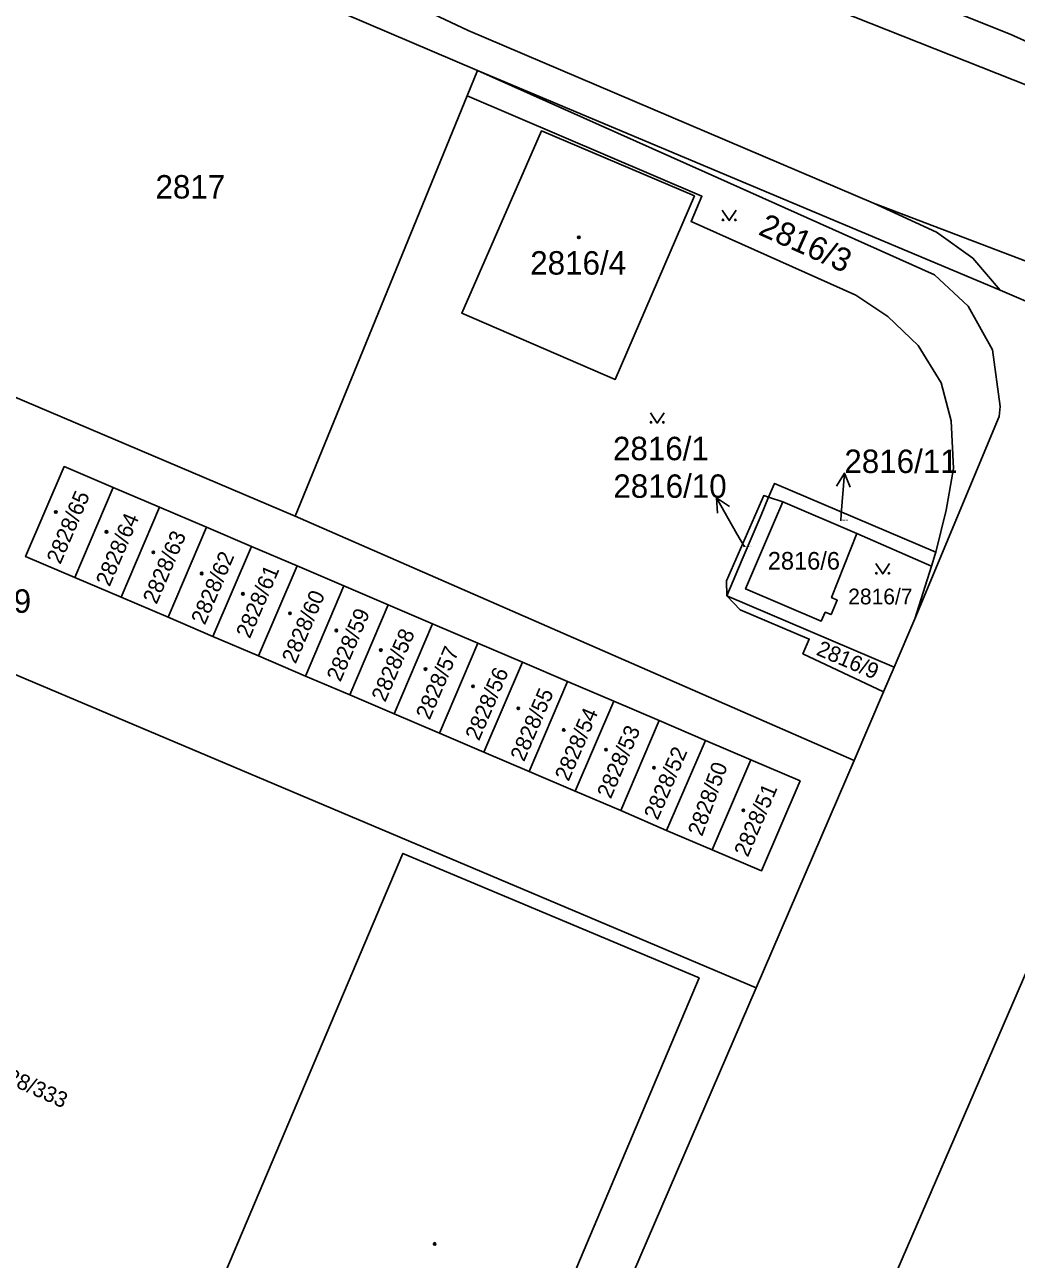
# Model space of a CAD drawing. Extents: x -596024 to -594475, y -1163820 to -1161957.
# Drawn here: x -594768.7 to -594696.7, y -1162300.1 to -1162210.5 of the extents above; entities that cross this region are included whole.
import ezdxf

# ---------------------------------------------------------------- set-up
doc = ezdxf.new("R2010")
doc.units = 0
for name, color, linetype in [('Level 1', 7, 'Continuous'), ('Level 4', 7, 'Continuous'), ('Level 5', 7, 'Continuous'), ('Level 57', 7, 'Continuous'), ('Level 60', 7, 'Continuous'), ('Vrstva 60', 7, 'Continuous')]:
    doc.layers.add(name, color=color, linetype=linetype)

msp = doc.modelspace()

# ---------------------------------------------------------------- linework, layer by layer
at = {"layer": 'Level 1'}
for points in [[(-594707.09, -1162223.48), (-594736.5, -1162210.95), (-594743.11, -1162207.81), (-594746.4, -1162206.15), (-594756.91, -1162200.41), (-594760.53, -1162198.75), (-594767.3, -1162195.88), (-594768.99, -1162199.68)], [(-594766.55, -1162200.72), (-594735.81, -1162213.85)], [(-594727.84, -1162201.98), (-594709.6, -1162209.52), (-594675.03, -1162223.23)], [(-594682.35, -1162217.53), (-594689.64, -1162214.64), (-594697.18, -1162211.23), (-594701.73, -1162209.41)], [(-594736.56, -1162215.7), (-594735.81, -1162213.85)], [(-594735.81, -1162213.85), (-594697.92, -1162229.81)], [(-594704.11, -1162253.66), (-594697.99, -1162238.96), (-594697.9, -1162238.25), (-594698.47, -1162234.14), (-594700.22, -1162230.95), (-594702.66, -1162228.69), (-594719.3, -1162221.23), (-594735.81, -1162213.85)], [(-594749.03, -1162246.2), (-594736.56, -1162215.7)], [(-594736.56, -1162215.7), (-594719.54, -1162222.99), (-594720.33, -1162224.82), (-594708.38, -1162230.17), (-594706.06, -1162231.71), (-594703.86, -1162233.81), (-594702.18, -1162236.53), (-594701.46, -1162239.29), (-594701.29, -1162242.73), (-594701.83, -1162245.76), (-594702.58, -1162248.81)], [(-594725.83, -1162236.28), (-594736.96, -1162231.48), (-594731.18, -1162218.24), (-594720.08, -1162222.96), (-594725.83, -1162236.28)], [(-594665.22, -1162239.43), (-594707.09, -1162223.48)], [(-594697.92, -1162229.81), (-594699.9, -1162227.48), (-594702.53, -1162225.59), (-594707.09, -1162223.48)], [(-594697.92, -1162229.81), (-594677.27, -1162238.66)], [(-594779.95, -1162233.06), (-594749.03, -1162246.2)], [(-594762.23, -1162244.12), (-594765.8, -1162242.6), (-594768.59, -1162249.13), (-594765.02, -1162250.66)], [(-594762.23, -1162244.12), (-594765.02, -1162250.66)], [(-594758.87, -1162245.55), (-594762.23, -1162244.12)], [(-594714.7, -1162244.83), (-594714.27, -1162243.83), (-594702.58, -1162248.81)], [(-594761.66, -1162252.08), (-594758.87, -1162245.55)], [(-594755.47, -1162247.01), (-594758.87, -1162245.55)], [(-594717.74, -1162251.98), (-594717.76, -1162250.89), (-594715.06, -1162244.71), (-594714.7, -1162244.83)], [(-594714.7, -1162244.83), (-594715.25, -1162246.14), (-594716.62, -1162249.35), (-594717.74, -1162251.98)], [(-594713.68, -1162245.17), (-594714.28, -1162246.56), (-594715.65, -1162249.78), (-594716.37, -1162251.48), (-594710.88, -1162253.82), (-594710.59, -1162253.17), (-594710.17, -1162253.34), (-594709.72, -1162252.3), (-594710.14, -1162252.11), (-594708.3, -1162247.46)], [(-594714.7, -1162244.83), (-594713.68, -1162245.17)], [(-594708.3, -1162247.46), (-594713.68, -1162245.17)], [(-594749.03, -1162246.2), (-594708.5, -1162263.93)], [(-594758.26, -1162253.54), (-594755.47, -1162247.01)], [(-594752.21, -1162248.4), (-594755.47, -1162247.01)], [(-594708.3, -1162247.46), (-594702.89, -1162249.82)], [(-594755, -1162254.93), (-594752.21, -1162248.4)], [(-594748.9, -1162249.81), (-594752.21, -1162248.4)], [(-594702.89, -1162249.82), (-594702.62, -1162248.97), (-594702.58, -1162248.81)], [(-594715.61, -1162280.43), (-594788.46, -1162249.61), (-594788.63, -1162249.99)], [(-594751.69, -1162256.34), (-594748.9, -1162249.81)], [(-594745.5, -1162251.26), (-594748.9, -1162249.81)], [(-594702.89, -1162249.82), (-594704.11, -1162253.66)], [(-594765.02, -1162250.66), (-594761.66, -1162252.08)], [(-594748.29, -1162257.8), (-594745.5, -1162251.26)], [(-594742.29, -1162252.64), (-594745.5, -1162251.26)], [(-594761.66, -1162252.08), (-594758.26, -1162253.54)], [(-594745.08, -1162259.17), (-594742.29, -1162252.64)], [(-594739.07, -1162254.01), (-594742.29, -1162252.64)], [(-594706.36, -1162258.94), (-594712.21, -1162256.18), (-594711.75, -1162255.12), (-594716.76, -1162253.01), (-594717.74, -1162251.98)], [(-594705.6, -1162257.16), (-594717.74, -1162251.98)], [(-594758.26, -1162253.54), (-594755, -1162254.93)], [(-594741.87, -1162260.54), (-594739.07, -1162254.01)], [(-594735.79, -1162255.41), (-594739.07, -1162254.01)], [(-594705.6, -1162257.16), (-594704.11, -1162253.66)], [(-594755, -1162254.93), (-594751.69, -1162256.34)], [(-594735.79, -1162255.41), (-594738.58, -1162261.94)], [(-594732.55, -1162256.8), (-594735.79, -1162255.41)], [(-594751.69, -1162256.34), (-594748.29, -1162257.8)], [(-594735.35, -1162263.33), (-594732.55, -1162256.8)], [(-594729.28, -1162258.19), (-594732.55, -1162256.8)], [(-594706.36, -1162258.94), (-594705.6, -1162257.16)], [(-594748.29, -1162257.8), (-594745.08, -1162259.17)], [(-594729.28, -1162258.19), (-594732.08, -1162264.72)], [(-594725.93, -1162259.63), (-594729.28, -1162258.19)], [(-594708.5, -1162263.93), (-594706.36, -1162258.94)], [(-594745.08, -1162259.17), (-594741.87, -1162260.54)], [(-594728.73, -1162266.16), (-594725.93, -1162259.63)], [(-594722.63, -1162261.04), (-594725.93, -1162259.63)], [(-594741.87, -1162260.54), (-594738.58, -1162261.94)], [(-594725.42, -1162267.57), (-594722.63, -1162261.04)], [(-594722.63, -1162261.04), (-594719.28, -1162262.47)], [(-594738.58, -1162261.94), (-594735.35, -1162263.33)], [(-594722.1, -1162269), (-594719.28, -1162262.47)], [(-594719.28, -1162262.47), (-594716, -1162263.88)], [(-594735.35, -1162263.33), (-594732.08, -1162264.72)], [(-594716, -1162263.88), (-594712.42, -1162265.41), (-594715.22, -1162271.94), (-594718.79, -1162270.41)], [(-594716, -1162263.88), (-594718.79, -1162270.41)], [(-594715.61, -1162280.43), (-594708.5, -1162263.93)], [(-594732.08, -1162264.72), (-594728.73, -1162266.16)], [(-594728.73, -1162266.16), (-594725.42, -1162267.57)], [(-594722.1, -1162269), (-594725.42, -1162267.57)], [(-594718.79, -1162270.41), (-594722.1, -1162269)], [(-594765.42, -1162327.81), (-594741.23, -1162270.67), (-594719.75, -1162279.71), (-594743.92, -1162336.9)], [(-594734.83, -1162369.04), (-594734.38, -1162367.99), (-594695.58, -1162278.29)], [(-594715.61, -1162280.43), (-594744.57, -1162347.6), (-594746.96, -1162353.57)]]:
    msp.add_lwpolyline(points, dxfattribs=at)
at = {"layer": 'Level 5'}
for points in [[(-594718.061, -1162224), (-594717.56, -1162224.75), (-594717.06, -1162224)], [(-594723.281, -1162238.69), (-594722.78, -1162239.44), (-594722.28, -1162238.69)], [(-594706.931, -1162249.64), (-594706.43, -1162250.39), (-594705.93, -1162249.64)]]:
    msp.add_lwpolyline(points, dxfattribs=at)
for centre, radius in [((-594718.01, -1162224.7), 0.05), ((-594717.111, -1162224.7), 0.05), ((-594728.47, -1162225.97), 0.09), ((-594728.47, -1162225.97), 0.0521), ((-594723.23, -1162239.39), 0.05), ((-594722.331, -1162239.39), 0.05), ((-594766.4, -1162245.9), 0.09), ((-594766.4, -1162245.9), 0.0521), ((-594762.72, -1162247.34), 0.09), ((-594762.72, -1162247.34), 0.0521), ((-594759.32, -1162248.83), 0.09), ((-594759.32, -1162248.83), 0.0521), ((-594755.82, -1162250.36), 0.09), ((-594755.82, -1162250.36), 0.0521), ((-594706.88, -1162250.34), 0.05), ((-594705.981, -1162250.34), 0.05), ((-594752.83, -1162251.84), 0.09), ((-594752.83, -1162251.84), 0.0521), ((-594749.42, -1162253.25), 0.09), ((-594749.42, -1162253.25), 0.0521), ((-594746.05, -1162254.5), 0.09), ((-594746.05, -1162254.5), 0.0521), ((-594742.83, -1162255.92), 0.09), ((-594742.83, -1162255.92), 0.0521), ((-594739.59, -1162257.3), 0.09), ((-594739.59, -1162257.3), 0.0521), ((-594736.14, -1162258.55), 0.09), ((-594736.14, -1162258.55), 0.0521), ((-594732.86, -1162260.15), 0.09), ((-594732.86, -1162260.15), 0.0521), ((-594729.56, -1162261.71), 0.09), ((-594729.56, -1162261.71), 0.0521), ((-594726.49, -1162263.14), 0.09), ((-594726.49, -1162263.14), 0.0521), ((-594723.02, -1162264.46), 0.09), ((-594723.02, -1162264.46), 0.0521), ((-594716.53, -1162267.55), 0.09), ((-594716.53, -1162267.55), 0.0521), ((-594738.92, -1162299.01), 0.09), ((-594738.92, -1162299.01), 0.0521)]:
    msp.add_circle(centre, radius, dxfattribs=at)
at = {"layer": 'Level 57'}
for p, q in [((-594709.434, -1162246.062), (-594709.21, -1162243.07)), ((-594716.998, -1162247.48), (-594718.476, -1162244.87)), ((-594709.47, -1162246.54), (-594709.434, -1162246.062)), ((-594716.46, -1162248.43), (-594716.998, -1162247.48))]:
    msp.add_line(p, q, dxfattribs=at)
for points in [[(-594709.783, -1162244.03), (-594709.21, -1162243.07), (-594708.786, -1162244.105)], [(-594718.419, -1162245.986), (-594718.476, -1162244.87), (-594717.549, -1162245.493)]]:
    msp.add_lwpolyline(points, dxfattribs=at)
at = {"layer": 'Level 60'}
for points in [[(-594689.64, -1162214.64), (-594697.18, -1162211.23), (-594701.73, -1162209.41), (-594652.12, -1162083.97), (-594635.64, -1162042.29), (-594631.38, -1162044.42), (-594625.07, -1162047.82), (-594653.97, -1162133.18), (-594655.49, -1162137.69), (-594667.25, -1162133.63), (-594675.19, -1162156.64), (-594678.9, -1162155.36), (-594685.92, -1162175.69), (-594674.83, -1162179.48), (-594670.08, -1162165.57), (-594665.39, -1162167.12), (-594682.35, -1162217.53)], [(-594702.53, -1162225.59), (-594699.9, -1162227.48), (-594697.92, -1162229.81), (-594735.81, -1162213.85), (-594766.55, -1162200.72), (-594768.99, -1162199.68), (-594767.3, -1162195.88), (-594760.53, -1162198.75), (-594756.91, -1162200.41), (-594746.4, -1162206.15), (-594743.11, -1162207.81), (-594736.5, -1162210.95), (-594707.09, -1162223.48)], [(-594697.18, -1162211.23), (-594689.64, -1162214.64), (-594682.35, -1162217.53), (-594681.39, -1162217.94), (-594669.86, -1162222.85), (-594671.99, -1162223.53), (-594675.03, -1162223.23), (-594709.6, -1162209.52), (-594727.84, -1162201.98), (-594728.96, -1162200.3), (-594730.51, -1162196.79), (-594727.89, -1162197.94), (-594720, -1162201.49), (-594718.63, -1162202.1), (-594713.96, -1162204.17), (-594705.43, -1162207.92), (-594701.73, -1162209.41)], [(-594735.81, -1162213.85), (-594736.56, -1162215.7), (-594749.03, -1162246.2), (-594779.95, -1162233.06), (-594766.55, -1162200.72)], [(-594816.82, -1162217.1), (-594798.1, -1162225.02), (-594779.95, -1162233.06), (-594749.03, -1162246.2), (-594708.5, -1162263.93), (-594715.61, -1162280.43), (-594788.46, -1162249.61), (-594788.63, -1162249.99), (-594837.24, -1162227.82), (-594832.36, -1162216.61), (-594829.67, -1162211.66)], [(-594697.99, -1162238.96), (-594704.11, -1162253.66), (-594702.89, -1162249.82), (-594702.62, -1162248.97), (-594702.58, -1162248.81), (-594701.83, -1162245.76), (-594701.29, -1162242.73), (-594701.46, -1162239.29), (-594702.18, -1162236.53), (-594703.86, -1162233.81), (-594706.06, -1162231.71), (-594708.38, -1162230.17), (-594720.33, -1162224.82), (-594719.54, -1162222.99), (-594736.56, -1162215.7), (-594735.81, -1162213.85), (-594719.3, -1162221.23), (-594702.66, -1162228.69), (-594700.22, -1162230.95), (-594698.47, -1162234.14), (-594697.9, -1162238.25)], [(-594708.38, -1162230.17), (-594706.06, -1162231.71), (-594703.86, -1162233.81), (-594702.18, -1162236.53), (-594701.46, -1162239.29), (-594701.29, -1162242.73), (-594701.83, -1162245.76), (-594702.58, -1162248.81), (-594714.27, -1162243.83), (-594714.7, -1162244.83), (-594715.06, -1162244.71), (-594717.76, -1162250.89), (-594717.74, -1162251.98), (-594716.76, -1162253.01), (-594711.75, -1162255.12), (-594712.21, -1162256.18), (-594706.36, -1162258.94), (-594708.5, -1162263.93), (-594749.03, -1162246.2), (-594736.56, -1162215.7), (-594719.54, -1162222.99), (-594720.33, -1162224.82)], [(-594736.96, -1162231.48), (-594725.83, -1162236.28), (-594720.08, -1162222.96), (-594731.18, -1162218.24)], [(-594725.83, -1162236.28), (-594736.96, -1162231.48), (-594731.18, -1162218.24), (-594720.08, -1162222.96)], [(-594676.95, -1162238.57), (-594677.27, -1162238.66), (-594697.92, -1162229.81), (-594699.9, -1162227.48), (-594702.53, -1162225.59), (-594707.09, -1162223.48), (-594665.22, -1162239.43), (-594668.99, -1162238.31), (-594673, -1162237.9)], [(-594765.02, -1162250.66), (-594761.66, -1162252.08), (-594758.26, -1162253.54), (-594755, -1162254.93), (-594751.69, -1162256.34), (-594748.29, -1162257.8), (-594745.08, -1162259.17), (-594741.87, -1162260.54), (-594738.58, -1162261.94), (-594735.35, -1162263.33), (-594732.08, -1162264.72), (-594728.73, -1162266.16), (-594725.42, -1162267.57), (-594722.1, -1162269), (-594718.79, -1162270.41), (-594715.22, -1162271.94), (-594712.42, -1162265.41), (-594716, -1162263.88), (-594719.28, -1162262.47), (-594722.63, -1162261.04), (-594725.93, -1162259.63), (-594729.28, -1162258.19), (-594732.55, -1162256.8), (-594735.79, -1162255.41), (-594739.07, -1162254.01), (-594742.29, -1162252.64), (-594745.5, -1162251.26), (-594748.9, -1162249.81), (-594752.21, -1162248.4), (-594755.47, -1162247.01), (-594758.87, -1162245.55), (-594762.23, -1162244.12), (-594765.8, -1162242.6), (-594768.59, -1162249.13)], [(-594762.23, -1162244.12), (-594765.02, -1162250.66), (-594768.59, -1162249.13), (-594765.8, -1162242.6)], [(-594765.02, -1162250.66), (-594762.23, -1162244.12), (-594758.87, -1162245.55), (-594761.66, -1162252.08)], [(-594713.68, -1162245.17), (-594714.7, -1162244.83), (-594714.27, -1162243.83), (-594702.58, -1162248.81), (-594702.62, -1162248.97), (-594702.89, -1162249.82), (-594708.3, -1162247.46)], [(-594761.66, -1162252.08), (-594758.87, -1162245.55), (-594755.47, -1162247.01), (-594758.26, -1162253.54)], [(-594717.74, -1162251.98), (-594717.76, -1162250.89), (-594715.06, -1162244.71), (-594714.7, -1162244.83), (-594715.25, -1162246.14), (-594716.62, -1162249.35)], [(-594704.11, -1162253.66), (-594705.6, -1162257.16), (-594717.74, -1162251.98), (-594716.62, -1162249.35), (-594715.25, -1162246.14), (-594714.7, -1162244.83), (-594713.68, -1162245.17), (-594714.28, -1162246.56), (-594715.65, -1162249.78), (-594716.37, -1162251.48), (-594710.88, -1162253.82), (-594710.59, -1162253.17), (-594710.17, -1162253.34), (-594709.72, -1162252.3), (-594710.14, -1162252.11), (-594708.3, -1162247.46), (-594702.89, -1162249.82)], [(-594716.37, -1162251.48), (-594715.65, -1162249.78), (-594714.28, -1162246.56), (-594713.68, -1162245.17), (-594708.3, -1162247.46), (-594710.14, -1162252.11), (-594709.72, -1162252.3), (-594710.17, -1162253.34), (-594710.59, -1162253.17), (-594710.88, -1162253.82)], [(-594758.26, -1162253.54), (-594755.47, -1162247.01), (-594752.21, -1162248.4), (-594755, -1162254.93)], [(-594755, -1162254.93), (-594752.21, -1162248.4), (-594748.9, -1162249.81), (-594751.69, -1162256.34)], [(-594788.46, -1162249.61), (-594715.61, -1162280.43), (-594744.57, -1162347.6), (-594746.96, -1162353.57), (-594748.04, -1162354.24), (-594750.51, -1162354.75), (-594752.49, -1162354.29), (-594804.19, -1162332.35), (-594810.1, -1162329.79), (-594821.58, -1162324.95), (-594788.63, -1162249.99)], [(-594751.69, -1162256.34), (-594748.9, -1162249.81), (-594745.5, -1162251.26), (-594748.29, -1162257.8)], [(-594748.29, -1162257.8), (-594745.5, -1162251.26), (-594742.29, -1162252.64), (-594745.08, -1162259.17)], [(-594745.08, -1162259.17), (-594742.29, -1162252.64), (-594739.07, -1162254.01), (-594741.87, -1162260.54)], [(-594706.36, -1162258.94), (-594712.21, -1162256.18), (-594711.75, -1162255.12), (-594716.76, -1162253.01), (-594717.74, -1162251.98), (-594705.6, -1162257.16)], [(-594741.87, -1162260.54), (-594739.07, -1162254.01), (-594735.79, -1162255.41), (-594738.58, -1162261.94)], [(-594738.58, -1162261.94), (-594735.79, -1162255.41), (-594732.55, -1162256.8), (-594735.35, -1162263.33)], [(-594735.35, -1162263.33), (-594732.55, -1162256.8), (-594729.28, -1162258.19), (-594732.08, -1162264.72)], [(-594732.08, -1162264.72), (-594729.28, -1162258.19), (-594725.93, -1162259.63), (-594728.73, -1162266.16)], [(-594722.63, -1162261.04), (-594725.42, -1162267.57), (-594728.73, -1162266.16), (-594725.93, -1162259.63)], [(-594725.42, -1162267.57), (-594722.63, -1162261.04), (-594719.28, -1162262.47), (-594722.1, -1162269)], [(-594722.1, -1162269), (-594719.28, -1162262.47), (-594716, -1162263.88), (-594718.79, -1162270.41)], [(-594718.79, -1162270.41), (-594716, -1162263.88), (-594712.42, -1162265.41), (-594715.22, -1162271.94)], [(-594719.75, -1162279.71), (-594741.23, -1162270.67), (-594765.42, -1162327.81), (-594776.1, -1162323.11), (-594786.46, -1162332.09), (-594759.51, -1162343.51), (-594760.04, -1162344.72), (-594749.17, -1162349.3), (-594743.92, -1162336.9)], [(-594741.23, -1162270.67), (-594719.75, -1162279.71), (-594743.92, -1162336.9), (-594765.42, -1162327.81)], [(-594695.58, -1162278.29), (-594648.27, -1162298.38), (-594683.2, -1162380.56), (-594691.28, -1162377.35), (-594692.6, -1162380.36), (-594694.11, -1162382.09), (-594696.5, -1162383.23), (-594699.4, -1162383.25), (-594734.83, -1162369.04), (-594734.38, -1162367.99)]]:
    msp.add_lwpolyline(points, close=True, dxfattribs=at)
msp.add_lwpolyline([(-594744.57, -1162347.6), (-594715.61, -1162280.43), (-594708.5, -1162263.93), (-594706.36, -1162258.94), (-594705.6, -1162257.16), (-594704.11, -1162253.66), (-594697.99, -1162238.96), (-594697.9, -1162238.25), (-594698.47, -1162234.14), (-594700.22, -1162230.95), (-594702.66, -1162228.69), (-594719.3, -1162221.23), (-594735.81, -1162213.85), (-594697.92, -1162229.81), (-594677.27, -1162238.66), (-594672.61, -1162240.67), (-594676.36, -1162241.26), (-594678.88, -1162242.68), (-594680.93, -1162244.85), (-594683.14, -1162249.47), (-594689.11, -1162263.33), (-594693.16, -1162272.69), (-594695.58, -1162278.29), (-594734.38, -1162367.99)], dxfattribs=at)
at = {"layer": 'Vrstva 60'}
for points in [[(-594629.59, -1162242.59), (-594657.76, -1162230.53), (-594675.03, -1162223.23), (-594709.6, -1162209.52), (-594727.84, -1162201.98), (-594745.73, -1162194.48), (-594753.62, -1162191.15), (-594774.97, -1162182.11), (-594787.37, -1162176.81), (-594787.91, -1162175.99), (-594787.84, -1162174.66), (-594787.2, -1162173.1), (-594796.68, -1162169.08), (-594806.44, -1162164.93), (-594816.34, -1162160.73), (-594826.54, -1162156.4), (-594829.67, -1162155.07), (-594841.52, -1162150.04), (-594852.23, -1162145.49)], [(-594858.18, -1162161.58), (-594821.3, -1162177.21), (-594802.86, -1162185.03), (-594784.49, -1162192.89), (-594768.99, -1162199.68), (-594767.3, -1162195.88), (-594760.53, -1162198.75), (-594756.91, -1162200.41), (-594746.4, -1162206.15), (-594743.11, -1162207.81), (-594736.5, -1162210.95), (-594707.09, -1162223.48), (-594665.22, -1162239.43), (-594660.59, -1162241.27), (-594597.6, -1162268.15)]]:
    msp.add_lwpolyline(points, dxfattribs=at)

# ---------------------------------------------------------------- texts
at = {"layer": 'Level 4'}
for s, height, p in [('2817', 1.7, (-594759.17, -1162223.15)), ('2816/4', 1.7, (-594731.99, -1162228.67)), ('2816/1', 1.7, (-594725.99, -1162242.14)), ('2816/11', 0.1, (-594709.47, -1162246.54)), ('2816/10', 0.1, (-594716.46, -1162248.43)), ('2816/6', 1.28, (-594714.763, -1162250.08)), ('2828/329', 1.7, (-594777.673, -1162253.21)), ('2816/7', 1.14, (-594708.93, -1162252.6))]:
    msp.add_text(s, height=height, dxfattribs=at).set_placement(p)
for s, height, rotation, p in [('2816/3', 1.7, 335.88198, (-594715.53, -1162225.73)), ('2828/65', 1.14, 66.89664, (-594766.07, -1162249.75)), ('2828/64', 1.14, 66.86496, (-594762.5, -1162251.37)), ('2828/63', 1.14, 66.86496, (-594759.09, -1162252.65)), ('2828/62', 1.14, 66.86496, (-594755.59, -1162254.15)), ('2828/61', 1.14, 66.86496, (-594752.33, -1162255.14)), ('2828/60', 1.14, 66.89664, (-594749.01, -1162256.97)), ('2828/59', 1.14, 66.86496, (-594745.76, -1162258.28)), ('2828/58', 1.14, 66.7908, (-594742.51, -1162259.75)), ('2816/9', 1.14, 336.89592, (-594711.316, -1162256.236)), ('2828/57', 1.14, 66.86496, (-594739.29, -1162261.04)), ('2828/56', 1.14, 66.7908, (-594735.71, -1162262.56)), ('2828/55', 1.14, 66.7908, (-594732.44, -1162264.07)), ('2828/54', 1.14, 66.7908, (-594729.21, -1162265.5)), ('2828/53', 1.14, 66.86496, (-594726.15, -1162266.77)), ('2828/52', 1.14, 66.64275, (-594722.75, -1162268.32)), ('2828/50', 1.14, 70.12395, (-594719.527, -1162269.494)), ('2828/51', 1.14, 66.7908, (-594716.21, -1162271)), ('2828/333', 1.14, 335.79999, (-594771.669, -1162286.582))]:
    msp.add_text(s, height=height, rotation=rotation, dxfattribs=at).set_placement(p)
at = {"layer": 'Level 57'}
for s, p in [('2816/11', (-594709.21, -1162243.07)), ('2816/10', (-594725.964, -1162244.87))]:
    msp.add_text(s, height=1.7, dxfattribs=at).set_placement(p)

doc.saveas('drawing.dxf')
